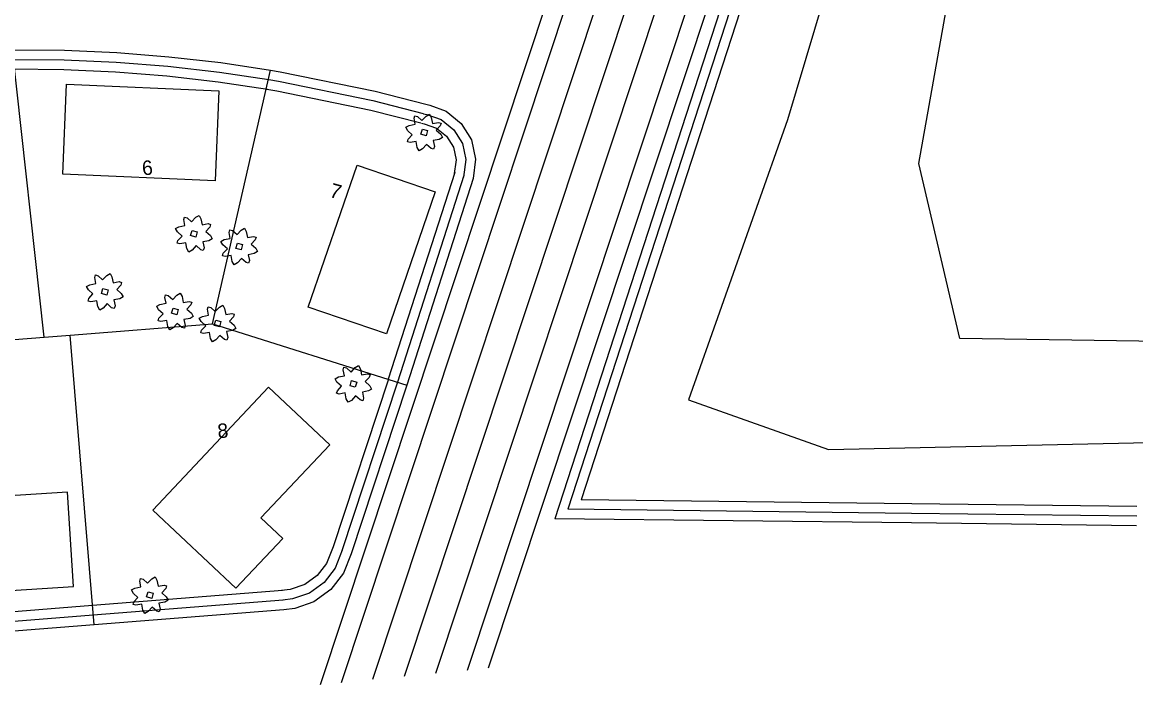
# Model space of a CAD drawing. Extents: x 1810019 to 1811399, y 1074962 to 1076105.
# Drawn here: x 1810473.9 to 1810935.4, y 1074973 to 1075247.7 of the extents above; entities that cross this region are included whole.
import ezdxf

# ---------------------------------------------------------------- set-up
doc = ezdxf.new("R2010")
doc.units = 0
for name, color, linetype in [('Environmental-New trees', 7, 'Continuous'), ('Property-Buildings', 7, 'Continuous'), ('Roadway-Centerline main', 7, 'Continuous'), ('Roadway-Edge of pavement', 7, 'Continuous'), ('Roadway-Edge of shoulder', 7, 'Continuous'), ('Roadway-Land lines', 7, 'Continuous'), ('Roadway-Sidewalks', 7, 'Continuous'), ('Text-Property owner', 7, 'Continuous')]:
    doc.layers.add(name, color=color, linetype=linetype)

msp = doc.modelspace()

# ---------------------------------------------------------------- linework, layer by layer
at = {"layer": 'Environmental-New trees'}
msp.add_lwpolyline([(1810835.88, 1075357.27), (1810791.12, 1075207.25), (1810749.98, 1075091.1), (1810808.06, 1075070.54), (1811029.46, 1075075.38), (1811082.69, 1075091.1), (1811029.46, 1075114.09), (1810862.5, 1075116.51), (1810845.56, 1075189.1), (1810869.76, 1075325.81), (1810838.3, 1075356.06)], dxfattribs=at)
for points in [[(1810633.57, 1075198.13), (1810633.88, 1075199.21), (1810635.57, 1075201.07), (1810633.71, 1075202.76), (1810632.93, 1075204.15), (1810634.28, 1075204.91), (1810636.79, 1075205.4), (1810636.32, 1075207.88), (1810636.62, 1075208.96), (1810637.71, 1075208.65), (1810639.57, 1075206.96), (1810641.26, 1075208.82), (1810642.65, 1075209.6), (1810643.43, 1075208.21), (1810643.9, 1075205.74), (1810646.37, 1075206.21), (1810647.46, 1075205.91), (1810647.09, 1075204.75), (1810645.46, 1075202.96), (1810647.32, 1075201.27), (1810648.1, 1075199.88), (1810646.74, 1075199.12), (1810644.24, 1075198.63), (1810644.71, 1075196.16), (1810644.4, 1075195.08), (1810643.32, 1075195.38), (1810641.46, 1075197.07), (1810639.77, 1075195.21), (1810638.38, 1075194.44), (1810637.6, 1075195.82), (1810637.13, 1075198.29), (1810634.66, 1075197.82)], [(1810639.74, 1075203.41), (1810641.9, 1075202.8), (1810641.29, 1075200.63), (1810639.13, 1075201.24)], [(1810538.1, 1075156.12), (1810538.41, 1075157.21), (1810540.1, 1075159.07), (1810538.24, 1075160.76), (1810537.46, 1075162.15), (1810538.81, 1075162.91), (1810541.32, 1075163.4), (1810540.85, 1075165.87), (1810541.15, 1075166.95), (1810542.24, 1075166.65), (1810544.1, 1075164.96), (1810545.79, 1075166.82), (1810547.18, 1075167.59), (1810547.96, 1075166.21), (1810548.43, 1075163.74), (1810550.9, 1075164.21), (1810551.98, 1075163.9), (1810551.61, 1075162.75), (1810549.99, 1075160.96), (1810551.85, 1075159.27), (1810552.62, 1075157.88), (1810551.27, 1075157.12), (1810548.76, 1075156.63), (1810549.24, 1075154.15), (1810548.93, 1075153.07), (1810547.85, 1075153.38), (1810545.99, 1075155.07), (1810544.29, 1075153.21), (1810542.91, 1075152.43), (1810542.13, 1075153.82), (1810541.66, 1075156.29), (1810539.18, 1075155.82)], [(1810544.26, 1075161.4), (1810546.43, 1075160.79), (1810545.82, 1075158.62), (1810543.65, 1075159.24)], [(1810556.9, 1075150.83), (1810557.21, 1075151.91), (1810558.9, 1075153.77), (1810557.04, 1075155.46), (1810556.26, 1075156.85), (1810557.61, 1075157.61), (1810560.12, 1075158.1), (1810559.65, 1075160.57), (1810559.95, 1075161.66), (1810561.04, 1075161.35), (1810562.9, 1075159.66), (1810564.59, 1075161.52), (1810565.98, 1075162.3), (1810566.76, 1075160.91), (1810567.23, 1075158.44), (1810569.7, 1075158.91), (1810570.79, 1075158.61), (1810570.42, 1075157.45), (1810568.79, 1075155.66), (1810570.65, 1075153.97), (1810571.43, 1075152.58), (1810570.07, 1075151.82), (1810567.57, 1075151.33), (1810568.04, 1075148.86), (1810567.73, 1075147.77), (1810566.65, 1075148.08), (1810564.79, 1075149.77), (1810563.1, 1075147.91), (1810561.71, 1075147.13), (1810560.93, 1075148.52), (1810560.46, 1075150.99), (1810557.99, 1075150.52)], [(1810563.07, 1075156.1), (1810565.23, 1075155.49), (1810564.62, 1075153.33), (1810562.46, 1075153.94)], [(1810501.19, 1075132.07), (1810501.5, 1075133.15), (1810503.19, 1075135.02), (1810501.33, 1075136.71), (1810500.55, 1075138.1), (1810501.9, 1075138.85), (1810504.41, 1075139.35), (1810503.94, 1075141.82), (1810504.24, 1075142.9), (1810505.33, 1075142.6), (1810507.19, 1075140.9), (1810508.88, 1075142.76), (1810510.27, 1075143.54), (1810511.05, 1075142.15), (1810511.52, 1075139.68), (1810513.99, 1075140.16), (1810515.07, 1075139.85), (1810514.7, 1075138.69), (1810513.07, 1075136.91), (1810514.94, 1075135.21), (1810515.71, 1075133.83), (1810514.36, 1075133.07), (1810511.85, 1075132.57), (1810512.33, 1075130.1), (1810512.02, 1075129.02), (1810510.94, 1075129.32), (1810509.08, 1075131.02), (1810507.38, 1075129.16), (1810506, 1075128.38), (1810505.22, 1075129.77), (1810504.75, 1075132.24), (1810502.27, 1075131.77)], [(1810507.35, 1075137.35), (1810509.52, 1075136.74), (1810508.91, 1075134.57), (1810506.74, 1075135.18)], [(1810530.25, 1075123.88), (1810530.55, 1075124.97), (1810532.25, 1075126.83), (1810530.39, 1075128.52), (1810529.61, 1075129.91), (1810530.96, 1075130.67), (1810533.47, 1075131.16), (1810532.99, 1075133.63), (1810533.3, 1075134.72), (1810534.38, 1075134.41), (1810536.24, 1075132.72), (1810537.94, 1075134.58), (1810539.33, 1075135.36), (1810540.1, 1075133.97), (1810540.58, 1075131.5), (1810543.05, 1075131.97), (1810544.13, 1075131.66), (1810543.76, 1075130.51), (1810542.13, 1075128.72), (1810543.99, 1075127.03), (1810544.77, 1075125.64), (1810543.42, 1075124.88), (1810540.91, 1075124.39), (1810541.38, 1075121.92), (1810541.08, 1075120.83), (1810540, 1075121.14), (1810538.14, 1075122.83), (1810536.44, 1075120.97), (1810535.05, 1075120.19), (1810534.28, 1075121.58), (1810533.8, 1075124.05), (1810531.33, 1075123.58)], [(1810536.41, 1075129.16), (1810538.58, 1075128.55), (1810537.97, 1075126.39), (1810535.8, 1075127)], [(1810547.91, 1075118.91), (1810548.22, 1075119.99), (1810549.91, 1075121.85), (1810548.05, 1075123.55), (1810547.27, 1075124.93), (1810548.62, 1075125.69), (1810551.13, 1075126.19), (1810550.66, 1075128.66), (1810550.96, 1075129.74), (1810552.05, 1075129.43), (1810553.91, 1075127.74), (1810555.6, 1075129.6), (1810556.99, 1075130.38), (1810557.77, 1075128.99), (1810558.24, 1075126.52), (1810560.71, 1075126.99), (1810561.79, 1075126.69), (1810561.42, 1075125.53), (1810559.79, 1075123.74), (1810561.66, 1075122.05), (1810562.43, 1075120.66), (1810561.08, 1075119.9), (1810558.57, 1075119.41), (1810559.05, 1075116.94), (1810558.74, 1075115.86), (1810557.66, 1075116.16), (1810555.8, 1075117.86), (1810554.1, 1075115.99), (1810552.72, 1075115.22), (1810551.94, 1075116.6), (1810551.47, 1075119.08), (1810548.99, 1075118.6)], [(1810554.07, 1075124.19), (1810556.24, 1075123.58), (1810555.63, 1075121.41), (1810553.46, 1075122.02)], [(1810604.19, 1075093.83), (1810604.49, 1075094.91), (1810606.19, 1075096.77), (1810604.32, 1075098.46), (1810603.55, 1075099.85), (1810604.9, 1075100.61), (1810607.41, 1075101.1), (1810606.93, 1075103.57), (1810607.24, 1075104.66), (1810608.32, 1075104.35), (1810610.18, 1075102.66), (1810611.88, 1075104.52), (1810613.26, 1075105.3), (1810614.04, 1075103.91), (1810614.52, 1075101.44), (1810616.99, 1075101.91), (1810618.07, 1075101.6), (1810617.7, 1075100.45), (1810616.07, 1075098.66), (1810617.93, 1075096.97), (1810618.71, 1075095.58), (1810617.36, 1075094.82), (1810614.85, 1075094.33), (1810615.32, 1075091.86), (1810615.02, 1075090.77), (1810613.93, 1075091.08), (1810612.07, 1075092.77), (1810610.38, 1075090.91), (1810608.99, 1075090.13), (1810608.21, 1075091.52), (1810607.74, 1075093.99), (1810605.27, 1075093.52)], [(1810610.35, 1075099.1), (1810612.52, 1075098.49), (1810611.91, 1075096.33), (1810609.74, 1075096.94)], [(1810519.86, 1075006.23), (1810520.16, 1075007.32), (1810521.85, 1075009.18), (1810519.99, 1075010.87), (1810519.22, 1075012.26), (1810520.57, 1075013.02), (1810523.08, 1075013.51), (1810522.6, 1075015.98), (1810522.91, 1075017.07), (1810523.99, 1075016.76), (1810525.85, 1075015.07), (1810527.55, 1075016.93), (1810528.93, 1075017.71), (1810529.71, 1075016.32), (1810530.18, 1075013.85), (1810532.66, 1075014.32), (1810533.74, 1075014.01), (1810533.37, 1075012.86), (1810531.74, 1075011.07), (1810533.6, 1075009.38), (1810534.38, 1075007.99), (1810533.03, 1075007.23), (1810530.52, 1075006.74), (1810530.99, 1075004.27), (1810530.69, 1075003.18), (1810529.6, 1075003.49), (1810527.74, 1075005.18), (1810526.05, 1075003.32), (1810524.66, 1075002.54), (1810523.88, 1075003.93), (1810523.41, 1075006.4), (1810520.94, 1075005.93)], [(1810526.02, 1075011.51), (1810528.19, 1075010.9), (1810527.58, 1075008.74), (1810525.41, 1075009.35)]]:
    msp.add_lwpolyline(points, close=True, dxfattribs=at)
at = {"layer": 'Property-Buildings'}
for points in [[(1810492.28, 1075222.02), (1810555.41, 1075219.32), (1810553.81, 1075182.02), (1810490.69, 1075184.72)], [(1810645.05, 1075177.34), (1810624.84, 1075118.47), (1810592.43, 1075129.59), (1810612.64, 1075188.47)], [(1810576, 1075096.32), (1810528.03, 1075045.43), (1810562.48, 1075012.95), (1810581.96, 1075033.62), (1810572.84, 1075042.22), (1810601.33, 1075072.44)], [(1810423.6, 1075009.1), (1810495.11, 1075013.64), (1810492.63, 1075052.82), (1810421.12, 1075048.28)]]:
    msp.add_lwpolyline(points, close=True, dxfattribs=at)
at = {"layer": 'Roadway-Centerline main'}
msp.add_line((1811006.18, 1076104.35), (1810632.15, 1074976.37), dxfattribs=at)
at = {"layer": 'Roadway-Edge of pavement'}
for p, q in [((1810980.71, 1076103.81), (1810606.02, 1074973.81)), ((1810993.45, 1076104.08), (1810619.08, 1074975.09)), ((1811018.91, 1076104.62), (1810645.22, 1074977.65)), ((1811031.64, 1076104.89), (1810658.29, 1074978.93))]:
    msp.add_line(p, q, dxfattribs=at)
at = {"layer": 'Roadway-Edge of shoulder'}
for p, q in [((1810972.23, 1076103.63), (1810597.31, 1074972.96)), ((1811040.13, 1076105.07), (1810667, 1074979.79))]:
    msp.add_line(p, q, dxfattribs=at)
at = {"layer": 'Roadway-Land lines'}
for p, q in [((1810946.95, 1075819.07), (1810694.59, 1075041.79)), ((1810482.93, 1075117.14), (1810469.79, 1075236.34)), ((1810552.77, 1075122.59), (1810576.73, 1075227.91)), ((1810660.76, 1075182.98), (1810633.23, 1075097.19)), ((1810493.71, 1075117.98), (1810552.77, 1075122.59)), ((1810552.77, 1075122.59), (1810633.23, 1075097.19)), ((1810482.93, 1075117.14), (1810493.71, 1075117.98)), ((1810503.65, 1074997.84), (1810493.71, 1075117.98)), ((1810408.27, 1075111.31), (1810482.93, 1075117.14)), ((1810633.23, 1075097.19), (1810610.19, 1075027.28)), ((1810842.47, 1075040.05), (1810694.59, 1075041.79)), ((1810935.78, 1075038.9), (1810842.47, 1075040.05)), ((1810582.33, 1075004.06), (1810503.65, 1074997.84)), ((1810503.65, 1074997.84), (1810416.91, 1074990.99))]:
    msp.add_line(p, q, dxfattribs=at)
for points in [[(1810469.79, 1075236.34), (1810491.37, 1075236.13), (1810513.03, 1075235.16), (1810534.65, 1075233.45), (1810556.2, 1075230.98), (1810576.73, 1075227.91)], [(1810576.73, 1075227.91), (1810580.85, 1075227.17), (1810620.14, 1075219.12), (1810641.13, 1075213.69)], [(1810641.13, 1075213.69), (1810642.76, 1075213.33), (1810649.57, 1075210.88), (1810655.86, 1075205.8), (1810660.1, 1075198.91), (1810661.8, 1075191), (1810660.76, 1075182.98)], [(1810610.19, 1075027.28), (1810607.06, 1075019.24), (1810601.77, 1075012.43), (1810594.77, 1075007.4), (1810586.82, 1075004.61), (1810582.33, 1075004.06)]]:
    msp.add_lwpolyline(points, dxfattribs=at)
at = {"layer": 'Roadway-Sidewalks'}
for p, q in [((1810949.56, 1075814.15), (1810700.07, 1075045.72)), ((1810952.49, 1075810.24), (1810705.56, 1075049.66)), ((1810653.15, 1075185.42), (1810625.61, 1075099.63)), ((1810656.95, 1075184.2), (1810629.42, 1075098.41)), ((1810625.63, 1075099.69), (1810602.59, 1075029.78)), ((1810629.43, 1075098.44), (1810606.39, 1075028.53)), ((1810842.57, 1075048.05), (1810705.56, 1075049.66)), ((1810842.52, 1075044.05), (1810700.07, 1075045.72)), ((1810935.83, 1075042.9), (1810842.52, 1075044.05)), ((1810935.88, 1075046.9), (1810842.57, 1075048.05)), ((1810581.7, 1075012.03), (1810503.02, 1075005.82)), ((1810582.02, 1075008.05), (1810503.33, 1075001.83)), ((1810503.02, 1075005.82), (1810416.28, 1074998.97)), ((1810503.33, 1075001.83), (1810416.6, 1074994.98))]:
    msp.add_line(p, q, dxfattribs=at)
for points in [[(1810469.72, 1075228.34), (1810491.15, 1075228.13), (1810512.54, 1075227.18), (1810533.88, 1075225.48), (1810555.15, 1075223.05), (1810575.54, 1075219.99)], [(1810469.76, 1075232.34), (1810491.26, 1075232.13), (1810512.79, 1075231.17), (1810534.27, 1075229.47), (1810555.67, 1075227.01), (1810576.14, 1075223.95)], [(1810576.03, 1075223.97), (1810580.1, 1075223.25), (1810619.23, 1075215.22), (1810640.13, 1075209.82)], [(1810575.33, 1075220.03), (1810579.35, 1075219.32), (1810618.33, 1075211.32), (1810639.13, 1075205.95)], [(1810639.37, 1075205.89), (1810640.52, 1075205.63), (1810645.59, 1075203.81), (1810649.77, 1075200.44), (1810652.57, 1075195.89), (1810653.69, 1075190.67), (1810652.83, 1075184.01)], [(1810640.25, 1075209.79), (1810641.64, 1075209.48), (1810647.58, 1075207.35), (1810652.82, 1075203.12), (1810656.34, 1075197.4), (1810657.75, 1075190.84), (1810656.8, 1075183.49)], [(1810602.74, 1075030.18), (1810600.03, 1075023.23), (1810596.17, 1075018.25), (1810591.04, 1075014.57), (1810584.98, 1075012.44), (1810581.36, 1075012)], [(1810606.46, 1075028.73), (1810603.54, 1075021.24), (1810598.97, 1075015.34), (1810592.9, 1075010.98), (1810585.9, 1075008.53), (1810581.84, 1075008.03)]]:
    msp.add_lwpolyline(points, dxfattribs=at)

# ---------------------------------------------------------------- texts
at = {"layer": 'Text-Property owner'}
for s, rotation, p in [('6', 4.4642, (1810523.76, 1075184.22)), ('7', 344.2655, (1810600.88, 1075175.36)), ('8', 4.4642, (1810555.04, 1075075.17))]:
    msp.add_text(s, height=6, rotation=rotation, dxfattribs=at).set_placement(p)

doc.saveas('drawing.dxf')
